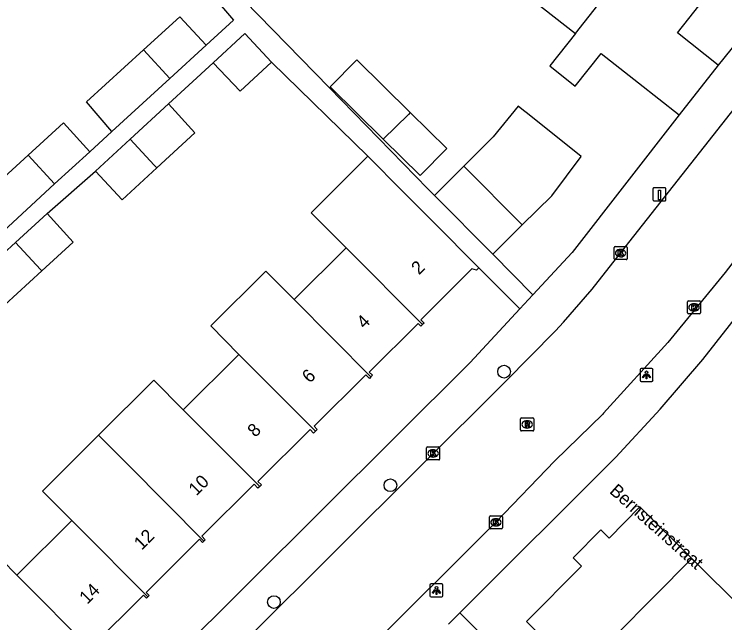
# Model space of a CAD drawing. Extents: x 159222 to 160346, y 381249 to 382166.
# Drawn here: x 160079.2 to 160133.8, y 381881.1 to 381927.9 of the extents above; entities that cross this region are included whole.
import ezdxf

# ---------------------------------------------------------------- set-up
doc = ezdxf.new("R2010")
doc.units = 0
for name, color, linetype in [('IMGEO_Boom', 7, 'Continuous'), ('IMGEO_Kolk', 7, 'Continuous'), ('IMGEO_Laadpaal', 7, 'Continuous'), ('IMGEO_Lichtpunt', 7, 'Continuous'), ('IMGEO_Openbare_ruimte_label', 7, 'Continuous'), ('IMGEO_Pand', 7, 'Continuous'), ('IMGEO_Pand_nummerreeks', 7, 'Continuous'), ('IMGEO_Rijbaan_lokaal_open', 7, 'Continuous'), ('IMGEO_Rioolput', 7, 'Continuous'), ('IMGEO_Voetpad_open', 7, 'Continuous')]:
    doc.layers.add(name, color=color, linetype=linetype)

msp = doc.modelspace()

# ---------------------------------------------------------------- linework, layer by layer
at = {"layer": 'IMGEO_Boom'}
for centre in [(160116.848, 381900.427), (160108.112, 381891.699), (160099.157, 381882.721)]:
    msp.add_circle(centre, 0.489, dxfattribs=at)
at = {"layer": 'IMGEO_Kolk'}
for p, q in [((160125.303, 381909.106), (160125.303, 381909.958)), ((160125.378, 381910.032), (160126.23, 381910.032)), ((160126.304, 381909.958), (160126.304, 381909.106)), ((160125.791, 381909.812), (160125.816, 381909.812)), ((160126.23, 381909.032), (160125.378, 381909.032)), ((160125.814, 381909.252), (160125.789, 381909.252)), ((160130.951, 381904.935), (160130.951, 381905.787)), ((160131.026, 381905.861), (160131.878, 381905.861)), ((160131.439, 381905.641), (160131.464, 381905.641)), ((160131.952, 381905.787), (160131.952, 381904.935)), ((160131.462, 381905.081), (160131.437, 381905.081)), ((160131.878, 381904.861), (160131.026, 381904.861)), ((160110.972, 381894.64), (160111.824, 381894.64)), ((160110.897, 381893.714), (160110.897, 381894.566)), ((160111.385, 381894.42), (160111.41, 381894.42)), ((160111.898, 381894.566), (160111.898, 381893.714)), ((160111.824, 381893.64), (160110.972, 381893.64)), ((160111.408, 381893.86), (160111.383, 381893.86)), ((160115.724, 381888.425), (160115.724, 381889.277)), ((160115.799, 381889.351), (160116.651, 381889.351)), ((160116.212, 381889.131), (160116.237, 381889.131)), ((160116.725, 381889.277), (160116.725, 381888.425)), ((160116.651, 381888.351), (160115.799, 381888.351)), ((160116.235, 381888.571), (160116.21, 381888.571))]:
    msp.add_line(p, q, dxfattribs=at)
for points in [[(160125.303, 381909.106), (160125.303, 381909.958)], [(160125.378, 381910.032), (160126.23, 381910.032)], [(160126.304, 381909.958), (160126.304, 381909.106)], [(160125.624, 381909.732), (160125.747, 381909.732), (160125.747, 381909.581), (160125.877, 381909.732), (160126.041, 381909.732), (160125.895, 381909.581), (160126.048, 381909.332), (160125.896, 381909.332), (160125.811, 381909.496), (160125.747, 381909.429), (160125.747, 381909.332), (160125.624, 381909.332), (160125.624, 381909.732)], [(160126.23, 381909.032), (160125.378, 381909.032)], [(160130.951, 381904.935), (160130.951, 381905.787)], [(160131.026, 381905.861), (160131.878, 381905.861)], [(160131.272, 381905.561), (160131.395, 381905.561), (160131.395, 381905.41), (160131.525, 381905.561), (160131.689, 381905.561), (160131.543, 381905.41), (160131.696, 381905.161), (160131.544, 381905.161), (160131.459, 381905.325), (160131.395, 381905.258), (160131.395, 381905.161), (160131.272, 381905.161), (160131.272, 381905.561)], [(160131.952, 381905.787), (160131.952, 381904.935)], [(160131.878, 381904.861), (160131.026, 381904.861)], [(160110.972, 381894.64), (160111.824, 381894.64)], [(160110.897, 381893.714), (160110.897, 381894.566)], [(160111.218, 381894.34), (160111.341, 381894.34), (160111.341, 381894.189), (160111.471, 381894.34), (160111.635, 381894.34), (160111.489, 381894.189), (160111.642, 381893.94), (160111.49, 381893.94), (160111.405, 381894.104), (160111.341, 381894.037), (160111.341, 381893.94), (160111.218, 381893.94), (160111.218, 381894.34)], [(160111.898, 381894.566), (160111.898, 381893.714)], [(160111.824, 381893.64), (160110.972, 381893.64)], [(160115.724, 381888.425), (160115.724, 381889.277)], [(160115.799, 381889.351), (160116.651, 381889.351)], [(160116.725, 381889.277), (160116.725, 381888.425)], [(160116.045, 381889.051), (160116.168, 381889.051), (160116.168, 381888.9), (160116.298, 381889.051), (160116.462, 381889.051), (160116.316, 381888.9), (160116.469, 381888.651), (160116.317, 381888.651), (160116.232, 381888.815), (160116.168, 381888.748), (160116.168, 381888.651), (160116.045, 381888.651), (160116.045, 381889.051)], [(160116.651, 381888.351), (160115.799, 381888.351)]]:
    msp.add_lwpolyline(points, dxfattribs=at)
for centre, start, end in [((160125.38, 381909.956), 91.552, 178.448), ((160125.38, 381909.956), 91.552, 178.448), ((160126.228, 381909.956), 1.552, 88.448), ((160126.228, 381909.956), 1.552, 88.448), ((160125.38, 381909.108), 181.552, 268.448), ((160125.38, 381909.108), 181.552, 268.448), ((160126.228, 381909.108), 271.552, 358.448), ((160126.228, 381909.108), 271.552, 358.448), ((160131.028, 381905.785), 91.552, 178.448), ((160131.028, 381905.785), 91.552, 178.448), ((160131.876, 381905.785), 1.552, 88.448), ((160131.876, 381905.785), 1.552, 88.448), ((160131.028, 381904.937), 181.552, 268.448), ((160131.028, 381904.937), 181.552, 268.448), ((160131.876, 381904.937), 271.552, 358.448), ((160131.876, 381904.937), 271.552, 358.448), ((160110.974, 381894.564), 91.552, 178.448), ((160110.974, 381894.564), 91.552, 178.448), ((160111.822, 381894.564), 1.552, 88.448), ((160111.822, 381894.564), 1.552, 88.448), ((160110.974, 381893.716), 181.552, 268.448), ((160110.974, 381893.716), 181.552, 268.448), ((160111.822, 381893.716), 271.552, 358.448), ((160111.822, 381893.716), 271.552, 358.448), ((160115.801, 381889.275), 91.552, 178.448), ((160115.801, 381889.275), 91.552, 178.448), ((160116.649, 381889.275), 1.552, 88.448), ((160116.649, 381889.275), 1.552, 88.448), ((160115.801, 381888.427), 181.552, 268.448), ((160115.801, 381888.427), 181.552, 268.448), ((160116.649, 381888.427), 271.552, 358.448), ((160116.649, 381888.427), 271.552, 358.448)]:
    msp.add_arc(centre, 0.0765, start, end, dxfattribs=at)
for centre, major_axis, ratio, start_param, end_param in [((160125.79, 381909.532), (-0.387, 0.002), 0.722429, 4.712389, 7.853982), ((160125.815, 381909.532), (-0.39, 0.002), 0.717154, 1.570796, 4.712389), ((160131.438, 381905.361), (-0.387, 0.002), 0.722429, 4.712389, 7.853982), ((160131.463, 381905.361), (-0.39, 0.002), 0.717154, 1.570796, 4.712389), ((160111.384, 381894.14), (-0.387, 0.002), 0.722429, 4.712389, 7.853982), ((160111.409, 381894.14), (-0.39, 0.002), 0.717154, 1.570796, 4.712389), ((160116.211, 381888.851), (-0.387, 0.002), 0.722429, 4.712389, 7.853982), ((160116.236, 381888.851), (-0.39, 0.002), 0.717154, 1.570796, 4.712389)]:
    msp.add_ellipse(centre, major_axis=major_axis, ratio=ratio, start_param=start_param, end_param=end_param, dxfattribs=at)
at = {"layer": 'IMGEO_Laadpaal'}
for p, q in [((160128.296, 381914.473), (160128.296, 381913.632)), ((160128.296, 381914.473), (160128.296, 381913.632)), ((160129.212, 381914.557), (160128.371, 381914.557)), ((160129.212, 381914.557), (160128.371, 381914.557)), ((160129.296, 381913.641), (160129.296, 381914.482)), ((160129.296, 381913.641), (160129.296, 381914.482)), ((160128.38, 381913.557), (160129.221, 381913.557)), ((160128.38, 381913.557), (160129.221, 381913.557))]:
    msp.add_line(p, q, dxfattribs=at)
msp.add_lwpolyline([(160128.711, 381914.37), (160128.871, 381914.37), (160128.871, 381913.637), (160128.711, 381913.637), (160128.711, 381914.37)], dxfattribs=at)
for centre, start, end in [((160128.374, 381914.479), 92.4484, 184.2845), ((160128.374, 381914.479), 92.4484, 184.2845), ((160129.218, 381914.479), 2.4484, 94.2845), ((160129.218, 381914.479), 2.4484, 94.2845), ((160128.374, 381913.635), 182.4484, 274.2845), ((160128.374, 381913.635), 182.4484, 274.2845), ((160129.218, 381913.635), 272.4484, 4.2845), ((160129.218, 381913.635), 272.4484, 4.2845)]:
    msp.add_arc(centre, 0.0779, start, end, dxfattribs=at)
at = {"layer": 'IMGEO_Lichtpunt'}
for p, q in [((160128.203, 381900.676), (160127.395, 381900.676)), ((160128.203, 381900.676), (160127.395, 381900.676)), ((160127.301, 381900.581), (160127.301, 381899.774)), ((160127.301, 381900.581), (160127.301, 381899.774)), ((160128.297, 381899.774), (160128.297, 381900.581)), ((160128.297, 381899.774), (160128.297, 381900.581)), ((160127.395, 381899.68), (160128.203, 381899.68)), ((160127.395, 381899.68), (160128.203, 381899.68)), ((160111.152, 381884.019), (160111.152, 381883.212)), ((160111.152, 381884.019), (160111.152, 381883.212)), ((160112.054, 381884.114), (160111.246, 381884.114)), ((160112.054, 381884.114), (160111.246, 381884.114)), ((160112.148, 381883.212), (160112.148, 381884.019)), ((160112.148, 381883.212), (160112.148, 381884.019)), ((160111.246, 381883.118), (160112.054, 381883.118)), ((160111.246, 381883.118), (160112.054, 381883.118))]:
    msp.add_line(p, q, dxfattribs=at)
for points in [[(160127.675, 381900.245), (160127.714, 381900.217), (160127.526, 381899.955), (160127.488, 381899.982), (160127.675, 381900.245)], [(160127.777, 381900.197), (160127.824, 381900.197), (160127.824, 381899.875), (160127.777, 381899.875), (160127.777, 381900.197)], [(160127.887, 381900.217), (160127.925, 381900.244), (160128.112, 381899.982), (160128.073, 381899.954), (160127.887, 381900.217)], [(160111.526, 381883.683), (160111.565, 381883.655), (160111.377, 381883.393), (160111.339, 381883.42), (160111.526, 381883.683)], [(160111.738, 381883.655), (160111.776, 381883.682), (160111.963, 381883.42), (160111.924, 381883.392), (160111.738, 381883.655)], [(160111.628, 381883.635), (160111.675, 381883.635), (160111.675, 381883.313), (160111.628, 381883.313), (160111.628, 381883.635)]]:
    msp.add_lwpolyline(points, dxfattribs=at)
for centre in [(160127.8, 381900.379), (160111.651, 381883.817)]:
    msp.add_circle(centre, 0.0994, dxfattribs=at)
for centre, start, end in [((160127.395, 381900.581), 90, 180), ((160127.395, 381900.581), 90, 180), ((160128.203, 381900.581), 0, 90), ((160128.203, 381900.581), 0, 90), ((160127.395, 381899.774), 180, 270), ((160127.395, 381899.774), 180, 270), ((160128.203, 381899.774), 270, 0), ((160128.203, 381899.774), 270, 360), ((160111.246, 381884.019), 90, 180), ((160111.246, 381884.019), 90, 180), ((160112.054, 381884.019), 0, 90), ((160112.054, 381884.019), 0, 90), ((160111.246, 381883.212), 180, 270), ((160111.246, 381883.212), 180, 270), ((160112.054, 381883.212), 270, 0), ((160112.054, 381883.212), 270, 360)]:
    msp.add_arc(centre, 0.0946, start, end, dxfattribs=at)
at = {"layer": 'IMGEO_Pand'}
for points in [[(160122.345, 381926.416), (160127.489, 381932.959)], [(160133.311, 381923.988), (160130.172, 381926.451), (160132.302, 381929.164), (160132.113, 381929.312), (160131.875, 381929.008), (160127.397, 381932.524), (160127.643, 381932.838), (160127.489, 381932.959)], [(160117.66, 381930.094), (160122.345, 381926.416)], [(160089.146, 381925.146), (160091.936, 381927.687), (160093.962, 381925.521)], [(160094.48, 381924.148), (160096.929, 381926.405), (160098.963, 381924.197)], [(160122.345, 381926.416), (160120.356, 381923.918), (160122.326, 381922.35), (160124.325, 381924.862), (160127.171, 381922.628), (160130.31, 381920.165)], [(160093.962, 381925.521), (160091.155, 381922.95)], [(160086.7, 381918.87), (160084.756, 381921.146), (160089.146, 381925.146)], [(160089.146, 381925.146), (160091.155, 381922.95)], [(160094.48, 381924.148), (160096.566, 381921.988), (160098.963, 381924.197)], [(160109.636, 381920.342), (160105.538, 381924.395), (160103.486, 381922.319), (160107.552, 381918.299)], [(160133.311, 381923.988), (160130.31, 381920.165)], [(160091.155, 381922.95), (160086.7, 381918.87)], [(160088.121, 381918.289), (160091.063, 381921)], [(160090.163, 381916.089), (160093.091, 381918.787), (160091.063, 381921)], [(160118.251, 381911.697), (160120.515, 381913.948), (160122.777, 381916.961), (160118.777, 381920.153), (160118.22, 381920.598), (160117.927, 381920.831), (160116.022, 381918.468), (160113.754, 381916.214)], [(160109.636, 381920.342), (160109.497, 381920.173), (160107.552, 381918.299)], [(160107.552, 381918.299), (160110.389, 381915.495), (160112.44, 381917.571), (160109.636, 381920.342)], [(160080.278, 381917.066), (160082.985, 381919.532), (160085.004, 381917.316)], [(160085.456, 381915.833), (160088.121, 381918.289)], [(160088.121, 381918.289), (160089.958, 381916.285), (160090.163, 381916.089)], [(160077.792, 381911.092), (160075.943, 381913.117), (160080.278, 381917.066)], [(160080.278, 381917.066), (160082.305, 381914.845)], [(160085.004, 381917.316), (160082.305, 381914.845)], [(160106.391, 381916.973), (160103.84, 381914.436), (160102.023, 381912.629), (160104.708, 381909.94)], [(160106.391, 381916.973), (160109.071, 381914.279), (160111.382, 381911.955), (160114.907, 381908.409)], [(160085.456, 381915.833), (160087.49, 381913.626), (160090.163, 381916.089)], [(160113.754, 381916.214), (160111.494, 381913.966)], [(160113.754, 381916.214), (160118.251, 381911.697)], [(160082.305, 381914.845), (160077.981, 381910.885), (160077.792, 381911.092)], [(160115.988, 381909.447), (160111.494, 381913.966)], [(160079.3, 381910.354), (160081.724, 381912.575)], [(160081.319, 381908.162), (160083.737, 381910.379), (160081.724, 381912.575)], [(160115.988, 381909.447), (160118.251, 381911.697)], [(160076.25, 381907.558), (160076.437, 381907.729), (160079.3, 381910.354)], [(160079.3, 381910.354), (160081.209, 381908.27), (160081.319, 381908.162)], [(160104.708, 381909.94), (160100.71, 381905.965)], [(160104.708, 381909.94), (160110.583, 381904.037)], [(160114.907, 381908.409), (160114.72, 381908.223), (160114.38, 381908.315), (160110.451, 381904.408), (160110.702, 381904.155), (160110.583, 381904.037)], [(160081.319, 381908.162), (160078.475, 381905.555), (160078.288, 381905.384), (160076.25, 381907.558)], [(160100.71, 381905.965), (160098.538, 381908.148), (160094.302, 381903.937), (160096.475, 381901.754)], [(160106.618, 381900.028), (160100.71, 381905.965)], [(160110.583, 381904.037), (160110.463, 381903.918), (160110.243, 381904.139), (160106.482, 381900.4), (160106.735, 381900.145), (160106.618, 381900.028)], [(160096.475, 381901.754), (160092.194, 381897.497)], [(160096.475, 381901.754), (160102.35, 381895.851)], [(160106.618, 381900.028), (160106.502, 381899.912), (160106.222, 381900.194), (160102.246, 381896.24), (160102.493, 381895.993), (160102.35, 381895.851)], [(160092.194, 381897.497), (160089.935, 381899.769), (160085.686, 381895.543)], [(160098.065, 381891.598), (160092.194, 381897.497)], [(160102.35, 381895.851), (160102.204, 381895.706), (160101.937, 381895.974), (160097.931, 381891.991), (160098.194, 381891.726), (160098.065, 381891.598)], [(160085.686, 381895.543), (160081.376, 381891.256), (160083.635, 381888.986)], [(160085.686, 381895.543), (160087.945, 381893.272), (160093.781, 381887.407)], [(160098.065, 381891.598), (160097.936, 381891.469), (160097.631, 381891.776), (160093.612, 381887.78), (160093.883, 381887.508), (160093.781, 381887.407)], [(160131.293, 381886.07), (160127.297, 381890.032), (160124.926, 381887.639), (160124.286, 381888.273), (160122.15, 381886.117), (160122.789, 381885.483), (160118.566, 381881.222), (160122.556, 381877.258)], [(160083.635, 381888.986), (160079.405, 381884.78)], [(160089.462, 381883.13), (160084.117, 381888.501), (160083.635, 381888.986)], [(160093.781, 381887.407), (160093.677, 381887.304), (160093.435, 381887.547), (160089.331, 381883.467), (160089.565, 381883.232), (160089.462, 381883.13)], [(160079.405, 381884.78), (160077.063, 381887.136), (160072.772, 381882.869)], [(160122.556, 381877.258), (160131.293, 381886.07)], [(160135.289, 381882.107), (160131.293, 381886.07)], [(160079.405, 381884.78), (160085.261, 381878.896)], [(160089.462, 381883.13), (160089.361, 381883.029), (160089.133, 381883.258), (160085.132, 381879.279), (160085.388, 381879.022), (160085.261, 381878.896)]]:
    msp.add_lwpolyline(points, dxfattribs=at)
at = {"layer": 'IMGEO_Rijbaan_lokaal_open'}
for points in [[(160002.99, 381786.2), (160012.11, 381795.292), (160116.933, 381899.648), (160120.802, 381903.57), (160121.409, 381904.226), (160123.621, 381906.761), (160125.502, 381909.146), (160137.982, 381924.966), (160137.985, 381924.969)], [(160143.594, 381920.544), (160142.505, 381919.215), (160137.727, 381913.117), (160133.839, 381908.037), (160129.443, 381902.654), (160124.504, 381897.226), (160124.44, 381897.155), (160120.742, 381893.578), (160116.227, 381888.855), (160106.101, 381878.782)]]:
    msp.add_lwpolyline(points, dxfattribs=at)
at = {"layer": 'IMGEO_Rioolput'}
for p, q in [((160118.125, 381895.944), (160118.125, 381896.796)), ((160118.2, 381896.87), (160119.052, 381896.87)), ((160119.126, 381896.796), (160119.126, 381895.944)), ((160118.613, 381896.65), (160118.638, 381896.65)), ((160119.052, 381895.87), (160118.2, 381895.87)), ((160118.636, 381896.09), (160118.611, 381896.09))]:
    msp.add_line(p, q, dxfattribs=at)
for points in [[(160118.125, 381895.944), (160118.125, 381896.796)], [(160118.2, 381896.87), (160119.052, 381896.87)], [(160119.126, 381896.796), (160119.126, 381895.944)], [(160118.714, 381896.568), (160118.462, 381896.57), (160118.462, 381896.17)], [(160118.462, 381896.17), (160118.586, 381896.17), (160118.586, 381896.332), (160118.597, 381896.332)], [(160118.64, 381896.489), (160118.586, 381896.489), (160118.586, 381896.408)], [(160118.586, 381896.408), (160118.638, 381896.408)], [(160118.644, 381896.303), (160118.715, 381896.17), (160118.855, 381896.17), (160118.79, 381896.296)], [(160119.052, 381895.87), (160118.2, 381895.87)]]:
    msp.add_lwpolyline(points, dxfattribs=at)
for centre, radius, start, end in [((160118.202, 381896.794), 0.0765, 91.552, 178.448), ((160118.202, 381896.794), 0.0765, 91.552, 178.448), ((160119.05, 381896.794), 0.0765, 1.552, 88.448), ((160119.05, 381896.794), 0.0765, 1.552, 88.448), ((160118.596, 381896.279), 0.0533, 26.0293, 88.6989), ((160118.622, 381896.597), 0.19, 274.7715, 282.9687), ((160118.646, 381896.393), 0.0964, 77.0061, 93.1865), ((160118.66, 381896.45), 0.0378, 276.6634, 79.6772), ((160118.713, 381896.458), 0.109, 350.3612, 89.416), ((160118.711, 381896.458), 0.112, 277.5842, 350.9817), ((160118.695, 381896.243), 0.108, 29.5134, 73.7905), ((160118.202, 381895.946), 0.0765, 181.552, 268.448), ((160118.202, 381895.946), 0.0765, 181.552, 268.448), ((160119.05, 381895.946), 0.0765, 271.552, 358.448), ((160119.05, 381895.946), 0.0765, 271.552, 358.448)]:
    msp.add_arc(centre, radius, start, end, dxfattribs=at)
for centre, major_axis, ratio, start_param, end_param in [((160118.612, 381896.37), (-0.387, 0.002), 0.722429, 4.712389, 7.853982), ((160118.637, 381896.37), (-0.39, 0.002), 0.717154, 1.570796, 4.712389)]:
    msp.add_ellipse(centre, major_axis=major_axis, ratio=ratio, start_param=start_param, end_param=end_param, dxfattribs=at)
at = {"layer": 'IMGEO_Voetpad_open'}
for points in [[(160086.272, 381938.014), (160094.493, 381929.287), (160096.06, 381927.443), (160093.962, 381925.521)], [(160111.494, 381913.966), (160110.998, 381914.475), (160103.419, 381922.251), (160094.713, 381931.184)], [(160135.68, 381926.914), (160133.311, 381923.988)], [(160091.063, 381921), (160092.628, 381922.442), (160094.48, 381924.148)], [(160098.963, 381924.197), (160106.391, 381916.973)], [(160113.448, 381881.888), (160125.439, 381893.854), (160128.859, 381897.542), (160132.127, 381901.365), (160146.756, 381920.002)], [(160130.31, 381920.165), (160122.078, 381909.579), (160119.067, 381906.332)], [(160086.7, 381918.87), (160085.004, 381917.316)], [(160081.724, 381912.575), (160085.456, 381915.833)], [(160119.067, 381906.332), (160115.988, 381909.447)], [(160118.056, 381905.241), (160114.907, 381908.409)], [(160118.056, 381905.241), (160119.067, 381906.332)], [(160079.939, 381867.002), (160114.243, 381901.129), (160118.056, 381905.241)], [(160112.581, 381881.023), (160113.448, 381881.888)], [(160113.448, 381881.888), (160122.049, 381873.351)]]:
    msp.add_lwpolyline(points, dxfattribs=at)

# ---------------------------------------------------------------- texts
at = {"layer": 'IMGEO_Openbare_ruimte_label'}
msp.add_text('Bernsteinstraat', height=1, rotation=318.3236, dxfattribs=at).set_placement((160124.891, 381891.153))
at = {"layer": 'IMGEO_Pand_nummerreeks'}
for s, rotation, p in [('2', 44.7861, (160110.309, 381907.825)), ('4', 44.7861, (160106.113, 381903.661)), ('6', 44.7881, (160101.915, 381899.494)), ('8', 44.7861, (160097.721, 381895.331)), ('10', 44.7861, (160093.197, 381890.839)), ('12', 44.7881, (160088.995, 381886.669)), ('14', 44.7881, (160084.8, 381882.505))]:
    msp.add_text(s, height=1, rotation=rotation, dxfattribs=at).set_placement(p)

doc.saveas('drawing.dxf')
